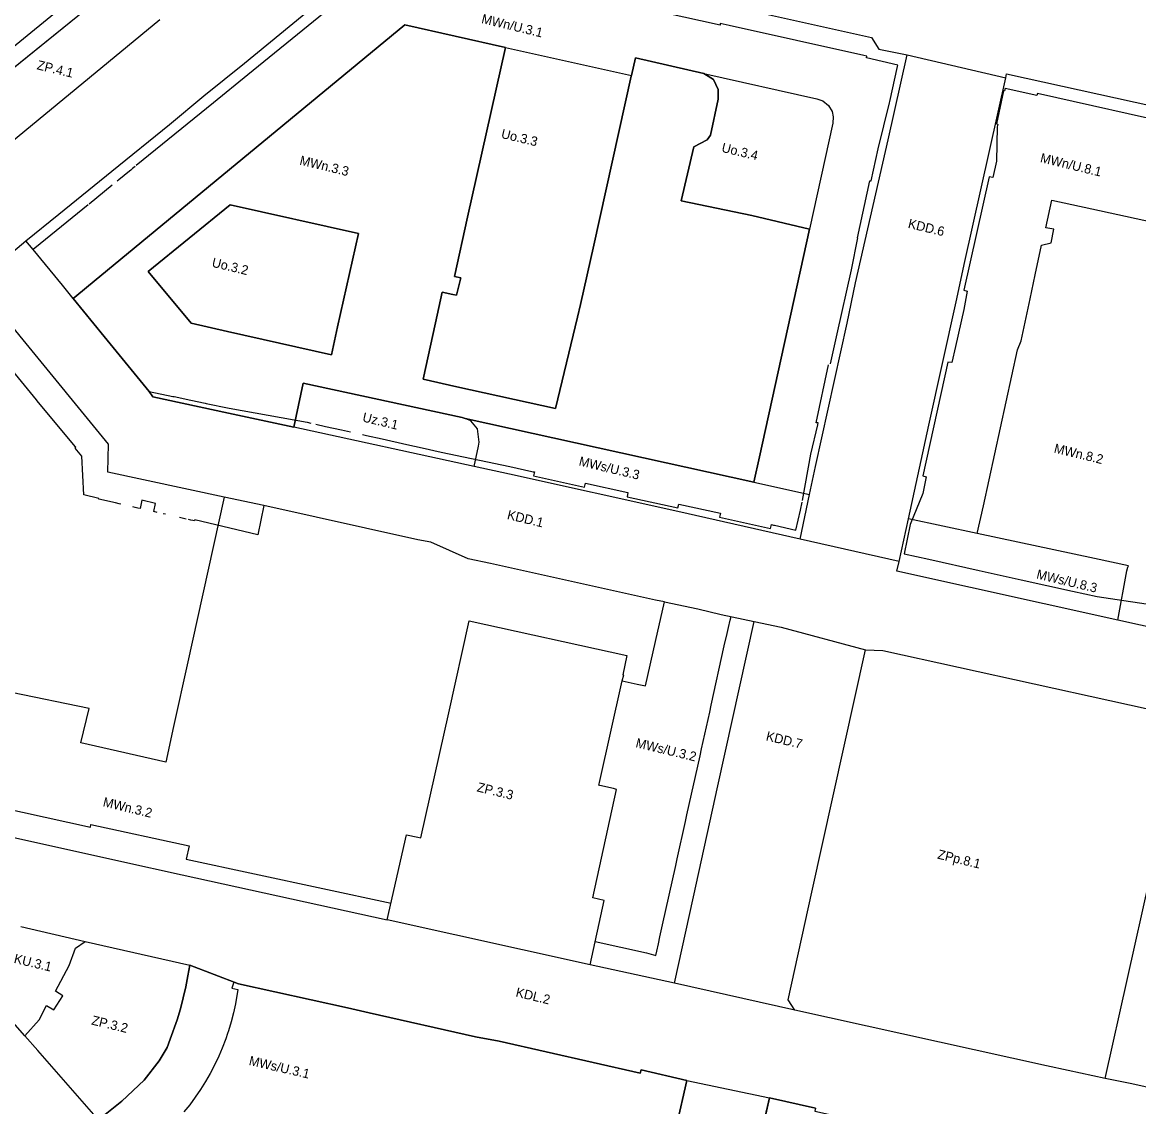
# Model space of a CAD drawing. Extents: x 7429686 to 7432896, y 5547954 to 5550600.
# Drawn here: x 7430853.5 to 7431331.5, y 5549169.6 to 5549633.8 of the extents above; entities that cross this region are included whole.
import ezdxf

# ---------------------------------------------------------------- set-up
doc = ezdxf.new("R2010")
doc.units = 0
for name, color, linetype in [('linie rozgraniczające', 7, 'Continuous'), ('obowiązująca linia zabudowy', 7, 'Continuous'), ('oznaczenia przeznaczeń', 7, 'Continuous')]:
    doc.layers.add(name, color=color, linetype=linetype)

msp = doc.modelspace()

# ---------------------------------------------------------------- linework, layer by layer
at = {"layer": 'linie rozgraniczające'}
for p, q in [((7430805.78, 5549578.76), (7430902.46, 5549657.05)), ((7431060.44, 5549622.97), (7431017.3, 5549632.77)), ((7431145.35, 5549611.95), (7431115.98, 5549618.56)), ((7431149.4, 5549609.29), (7431145.35, 5549611.95)), ((7431151.42, 5549605.07), (7431149.4, 5549609.29)), ((7431151.36, 5549600.9), (7431151.42, 5549605.07)), ((7431148.1, 5549585.52), (7431151.36, 5549600.9)), ((7431146.68, 5549583.47), (7431148.1, 5549585.52)), ((7431165.82, 5549551.11), (7431135.61, 5549557.36)), ((7431190.58, 5549545.27), (7431165.82, 5549551.11)), ((7430997.37, 5549543.36), (7430988.46, 5549503.38)), ((7430925.73, 5549504.96), (7430907.34, 5549527.16)), ((7430941.32, 5549501.47), (7430925.73, 5549504.96)), ((7430985.82, 5549491.51), (7430941.32, 5549501.47)), ((7430988.46, 5549503.38), (7430985.82, 5549491.51)), ((7431043.13, 5549464.16), (7431166.77, 5549436.9)), ((7430925.21, 5549230.15), (7430924.39, 5549225.55)), ((7430946.07, 5549222.14), (7430925.21, 5549230.15)), ((7430924.39, 5549225.55), (7430923.56, 5549220.95)), ((7430992.68, 5549211.86), (7430946.07, 5549222.14)), ((7430921.28, 5549211.46), (7430919.72, 5549206.79)), ((7431057.72, 5549197.56), (7431047.54, 5549199.55)), ((7431137.98, 5549180.79), (7431118.39, 5549185.34)), ((7431173.39, 5549173.33), (7431168.91, 5549153.67)), ((7431193.1, 5549168.9), (7431173.39, 5549173.33))]:
    msp.add_line(p, q, dxfattribs=at)
for points in [[(7430948.56, 5549616.32), (7431013.19, 5549669.37)], [(7430902.46, 5549657.05), (7430805.78, 5549578.76)], [(7431154.15, 5549641.32), (7431217.12, 5549627.23)], [(7430912.39, 5549634.82), (7430824.34, 5549562.34)], [(7431017.3, 5549632.77), (7430884.31, 5549522.94), (7430876.89, 5549516.82), (7430875.29, 5549515.5)], [(7430875.29, 5549515.5), (7430876.89, 5549516.82), (7430884.31, 5549522.94), (7431017.3, 5549632.77), (7431060.44, 5549622.97)], [(7431217.12, 5549627.23), (7431220.25, 5549622.33)], [(7431041.28, 5549524.35), (7431038.58, 5549525.03), (7431044.08, 5549550.36), (7431060.44, 5549622.97)], [(7431060.44, 5549622.97), (7431044.08, 5549550.36)], [(7431060.44, 5549622.97), (7431114.3, 5549611.01)], [(7431115.98, 5549618.56), (7431114.3, 5549611.01), (7431114.25, 5549610.75)], [(7431114.3, 5549611.01), (7431115.98, 5549618.56), (7431145.35, 5549611.95)], [(7431220.25, 5549622.33), (7431232.35, 5549619.87)], [(7431224.18, 5549583.49), (7431232.35, 5549619.87)], [(7431232.35, 5549619.87), (7431274.57, 5549610.08)], [(7430931.23, 5549602.33), (7430948.56, 5549616.32)], [(7431044.08, 5549550.36), (7431038.58, 5549525.03), (7431041.28, 5549524.35), (7431039.37, 5549516.99), (7431037.88, 5549517.3), (7431033.27, 5549518.26), (7431030.39, 5549505.08), (7431025.15, 5549481), (7431039.49, 5549477.82), (7431081.71, 5549468.44), (7431091.22, 5549507.55), (7431092.54, 5549512.97), (7431098.15, 5549538.37), (7431114.25, 5549610.75), (7431114.3, 5549611.01)], [(7431114.25, 5549610.75), (7431098.15, 5549538.37), (7431092.54, 5549512.97), (7431091.22, 5549507.55), (7431081.71, 5549468.44)], [(7431145.35, 5549611.95), (7431149.4, 5549609.29), (7431151.42, 5549605.07), (7431151.36, 5549600.9), (7431148.1, 5549585.52), (7431146.68, 5549583.47), (7431141.02, 5549580.54), (7431135.61, 5549557.36), (7431165.82, 5549551.11), (7431190.58, 5549545.27)], [(7431145.35, 5549611.95), (7431193.69, 5549601.09)], [(7431257.06, 5549531.37), (7431274.57, 5549610.08)], [(7431274.57, 5549610.08), (7431274.89, 5549611.78)], [(7431274.89, 5549611.78), (7431345.61, 5549596.13)], [(7430916.56, 5549590.09), (7430931.23, 5549602.33)], [(7431193.69, 5549601.09), (7431196.23, 5549600.17)], [(7431196.23, 5549600.17), (7431198.63, 5549598.17)], [(7431198.63, 5549598.17), (7431200.21, 5549595.65)], [(7431200.21, 5549595.65), (7431200.74, 5549593.29)], [(7430891.82, 5549570.05), (7430916.56, 5549590.09)], [(7431200.57, 5549590.67), (7431190.58, 5549545.27)], [(7431200.74, 5549593.29), (7431200.57, 5549590.67)], [(7431135.61, 5549557.36), (7431141.02, 5549580.54), (7431146.68, 5549583.47)], [(7431210.29, 5549522.31), (7431224.18, 5549583.49)], [(7430869.05, 5549551.6), (7430891.82, 5549570.05)], [(7431291.74, 5549545.78), (7431294.36, 5549557.7)], [(7431294.36, 5549557.7), (7431311.49, 5549553.94)], [(7430985.82, 5549491.51), (7430988.46, 5549503.38), (7430997.37, 5549543.36), (7430942.5, 5549555.67), (7430907.34, 5549527.16), (7430925.73, 5549504.96)], [(7430907.34, 5549527.16), (7430942.5, 5549555.67), (7430997.37, 5549543.36)], [(7431311.49, 5549553.94), (7431344.79, 5549546.64)], [(7430854.97, 5549540.19), (7430869.05, 5549551.6)], [(7431166.77, 5549436.9), (7431169.16, 5549447.78), (7431190.58, 5549545.27)], [(7431190.58, 5549545.27), (7431169.16, 5549447.78), (7431166.77, 5549436.9)], [(7431295.13, 5549545.22), (7431291.74, 5549545.78)], [(7431294.06, 5549539.34), (7431295.13, 5549545.22)], [(7430833.75, 5549522.41), (7430854.97, 5549540.19)], [(7430858.13, 5549536.5), (7430854.97, 5549540.19)], [(7431287.21, 5549525.72), (7431289.93, 5549538.36)], [(7431289.93, 5549538.36), (7431294.06, 5549539.34)], [(7430870.63, 5549521.22), (7430858.13, 5549536.5)], [(7431253.27, 5549514.13), (7431257.06, 5549531.37)], [(7431081.71, 5549468.44), (7431039.49, 5549477.82), (7431025.15, 5549481), (7431030.39, 5549505.08), (7431033.27, 5549518.26), (7431037.88, 5549517.3), (7431039.37, 5549516.99), (7431041.28, 5549524.35)], [(7431285, 5549515.41), (7431287.21, 5549525.72)], [(7430853.78, 5549497.92), (7430833.75, 5549522.41)], [(7430875.29, 5549515.5), (7430870.63, 5549521.22)], [(7431206.62, 5549504.99), (7431210.29, 5549522.31)], [(7430875.29, 5549515.5), (7430888.55, 5549499.33), (7430907.83, 5549475.8), (7430909.41, 5549473.4), (7430941.7, 5549466.42), (7430969.78, 5549460.53)], [(7430969.78, 5549460.53), (7430941.7, 5549466.42), (7430909.41, 5549473.4), (7430907.83, 5549475.8), (7430888.55, 5549499.33), (7430875.29, 5549515.5)], [(7431241.65, 5549461.33), (7431253.27, 5549514.13)], [(7431281.12, 5549497.39), (7431285, 5549515.41)], [(7430925.73, 5549504.96), (7430941.32, 5549501.47), (7430985.82, 5549491.51)], [(7431193.11, 5549443.59), (7431206.62, 5549504.99)], [(7430890.32, 5549453.23), (7430853.78, 5549497.92)], [(7431279.64, 5549493.6), (7431281.12, 5549497.39)], [(7431264.99, 5549426.8), (7431279.64, 5549493.6)], [(7430969.78, 5549460.53), (7430973.73, 5549479.35), (7431041.84, 5549464.68), (7431043.13, 5549464.16)], [(7431043.13, 5549464.16), (7431041.84, 5549464.68), (7430973.73, 5549479.35), (7430969.78, 5549460.53)], [(7431045.53, 5549463.19), (7431043.13, 5549464.16)], [(7431166.77, 5549436.9), (7431043.13, 5549464.16)], [(7431048.41, 5549459.82), (7431045.53, 5549463.19)], [(7431232.88, 5549421.31), (7431241.65, 5549461.33)], [(7431046.95, 5549443.71), (7430969.78, 5549460.53)], [(7431049.16, 5549454.04), (7431048.41, 5549459.82)], [(7430890.1, 5549441.28), (7430890.32, 5549453.23)], [(7431046.95, 5549443.71), (7431048.8, 5549452.38)], [(7431048.8, 5549452.38), (7431049.16, 5549454.04)], [(7431062.15, 5549440.39), (7431046.95, 5549443.71)], [(7431190.57, 5549431.65), (7431193.11, 5549443.59)], [(7430939.91, 5549430.52), (7430890.1, 5549441.28)], [(7431134.22, 5549424.35), (7431062.15, 5549440.39)], [(7431166.77, 5549436.9), (7431190.57, 5549431.65)], [(7430939.91, 5549430.52), (7430926.22, 5549368.37)], [(7430956.92, 5549426.98), (7430939.91, 5549430.52)], [(7431186.51, 5549412.5), (7431190.57, 5549431.65)], [(7431022.86, 5549412.27), (7430956.92, 5549426.98)], [(7431186.51, 5549412.5), (7431134.22, 5549424.35)], [(7431262.39, 5549414.97), (7431264.99, 5549426.8)], [(7431228.87, 5549403.02), (7431232.88, 5549421.31)], [(7431262.39, 5549414.97), (7431232.88, 5549421.31)], [(7431312.51, 5549404.2), (7431262.39, 5549414.97)], [(7431028.36, 5549411.26), (7431022.86, 5549412.27)], [(7431044.33, 5549404.06), (7431028.36, 5549411.26)], [(7431228.87, 5549403.02), (7431186.51, 5549412.5)], [(7431053.95, 5549402.07), (7431044.33, 5549404.06)], [(7431327.11, 5549401.06), (7431312.51, 5549404.2)], [(7431124.6, 5549386.43), (7431053.95, 5549402.07)], [(7431227.95, 5549398.82), (7431228.87, 5549403.02)], [(7431322.62, 5549377.89), (7431227.95, 5549398.82)], [(7431322.62, 5549377.89), (7431326.44, 5549398.92)], [(7431326.44, 5549398.92), (7431326.91, 5549400.58)], [(7431326.91, 5549400.58), (7431327.11, 5549401.06)], [(7431124.55, 5549368.66), (7431128.39, 5549385.66)], [(7431128.39, 5549385.66), (7431124.6, 5549386.43)], [(7431128.39, 5549385.66), (7431142.66, 5549382.73)], [(7431142.66, 5549382.73), (7431152.75, 5549380.32)], [(7431152.75, 5549380.32), (7431166.9, 5549377.31)], [(7431036.05, 5549338.21), (7431044.85, 5549377.6)], [(7431044.85, 5549377.6), (7431112.37, 5549362.8)], [(7431151.26, 5549306.99), (7431166.9, 5549377.31)], [(7431166.9, 5549377.31), (7431178.43, 5549374.88)], [(7431178.43, 5549374.88), (7431214.54, 5549365.17)], [(7431444.94, 5549350.86), (7431322.62, 5549377.89)], [(7430926.22, 5549368.37), (7430924.39, 5549360.07)], [(7431120.27, 5549349.73), (7431124.55, 5549368.66)], [(7431112.37, 5549362.8), (7431110.56, 5549354.5)], [(7431191.59, 5549261.43), (7431214.54, 5549365.17)], [(7431214.54, 5549365.17), (7431221.89, 5549364.84)], [(7431221.89, 5549364.84), (7431351.47, 5549336.38)], [(7430924.39, 5549360.07), (7430918.27, 5549332.28)], [(7431100.69, 5549308.41), (7431110.39, 5549351.83)], [(7431110.39, 5549351.85), (7431111.1, 5549354.42)], [(7431110.39, 5549351.83), (7431110.39, 5549351.85)], [(7431110.39, 5549351.83), (7431116.68, 5549350.49)], [(7431110.56, 5549354.5), (7431111.1, 5549354.42)], [(7430882.06, 5549340.05), (7430848.84, 5549346.95)], [(7431116.68, 5549350.49), (7431120.27, 5549349.73)], [(7430878.53, 5549325.34), (7430882.06, 5549340.05)], [(7431024.08, 5549284.61), (7431036.05, 5549338.21)], [(7430918.27, 5549332.28), (7430914.91, 5549317.04)], [(7430881.65, 5549324.62), (7430878.53, 5549325.34)], [(7430914.91, 5549317.04), (7430881.65, 5549324.62)], [(7431100.29, 5549307.16), (7431100.69, 5549308.41)], [(7431097.72, 5549259.01), (7431107.87, 5549305.41)], [(7431100.78, 5549307.05), (7431100.29, 5549307.16)], [(7431106.56, 5549305.73), (7431100.78, 5549307.05)], [(7431107.87, 5549305.41), (7431106.56, 5549305.73)], [(7431140.83, 5549259.37), (7431151.26, 5549306.99)], [(7430833.66, 5549288.37), (7430896.14, 5549274.49)], [(7431009.76, 5549249.53), (7431017.92, 5549285.99)], [(7431017.92, 5549285.99), (7431022.8, 5549284.9)], [(7431022.8, 5549284.9), (7431024.08, 5549284.61)], [(7430896.14, 5549274.49), (7430921.88, 5549268.85)], [(7430921.88, 5549268.85), (7431009.76, 5549249.53)], [(7431317.19, 5549181.59), (7431336.22, 5549267.3)], [(7431181.37, 5549215.29), (7431191.59, 5549261.43)], [(7431096.56, 5549230.3), (7431102.59, 5549257.84)], [(7431102.59, 5549257.84), (7431097.72, 5549259.01)], [(7431132.72, 5549222.39), (7431140.83, 5549259.37)], [(7430852.85, 5549246.65), (7430880.45, 5549240.36)], [(7431096.56, 5549230.3), (7431009.76, 5549249.53)], [(7430873.55, 5549229.96), (7430876.26, 5549237.45)], [(7430876.26, 5549237.45), (7430880.45, 5549240.36)], [(7430880.45, 5549240.36), (7430925.21, 5549230.15)], [(7430867.65, 5549218.97), (7430873.55, 5549229.96)], [(7430886.17, 5549163.92), (7430896.16, 5549171.92), (7430905.64, 5549181), (7430912.06, 5549189.23), (7430915.45, 5549194.85), (7430916.8, 5549198.49), (7430919.72, 5549206.79), (7430921.28, 5549211.46), (7430922.42, 5549216.2), (7430923.56, 5549220.95), (7430924.39, 5549225.55), (7430925.21, 5549230.15)], [(7430925.21, 5549230.15), (7430946.07, 5549222.14), (7430992.68, 5549211.86), (7431002.04, 5549209.78), (7431047.54, 5549199.55), (7431057.72, 5549197.56), (7431118.08, 5549183.93), (7431118.39, 5549185.34), (7431137.98, 5549180.79)], [(7431132.72, 5549222.39), (7431096.56, 5549230.3)], [(7431184.19, 5549210.87), (7431132.72, 5549222.39)], [(7430866.94, 5549211.08), (7430870.85, 5549217.08)], [(7430870.85, 5549217.08), (7430867.65, 5549218.97)], [(7430923.56, 5549220.95), (7430922.42, 5549216.2), (7430921.28, 5549211.46)], [(7430860.67, 5549206.73), (7430863.87, 5549212.92)], [(7430863.87, 5549212.92), (7430866.94, 5549211.08)], [(7431184.19, 5549210.87), (7431181.37, 5549215.29)], [(7430854.62, 5549199.88), (7430846.27, 5549209.39)], [(7431047.54, 5549199.55), (7431002.04, 5549209.78), (7430992.68, 5549211.86)], [(7431291.99, 5549187.13), (7431184.19, 5549210.87)], [(7430854.62, 5549199.88), (7430860.67, 5549206.73)], [(7430919.72, 5549206.79), (7430916.8, 5549198.49), (7430915.45, 5549194.85), (7430912.06, 5549189.23), (7430905.64, 5549181)], [(7430860.07, 5549193.67), (7430854.62, 5549199.88)], [(7430886.17, 5549163.92), (7430860.07, 5549193.67)], [(7431118.39, 5549185.34), (7431118.08, 5549183.93), (7431057.72, 5549197.56)], [(7431301.28, 5549185.08), (7431291.99, 5549187.13)], [(7431317.19, 5549181.59), (7431301.28, 5549185.08)], [(7430905.64, 5549181), (7430896.16, 5549171.92), (7430886.17, 5549163.92)], [(7431099.36, 5548971.58), (7431107.22, 5549007.82), (7431113.56, 5549037.12), (7431098.96, 5549039.76), (7431100.87, 5549049.04), (7431122.56, 5549148.42), (7431126.27, 5549162.98), (7431133.65, 5549161.37), (7431137.98, 5549180.79)], [(7431137.98, 5549180.79), (7431133.65, 5549161.37), (7431126.27, 5549162.98)], [(7431137.98, 5549180.79), (7431173.39, 5549173.33)], [(7431327.86, 5549179.5), (7431317.19, 5549181.59)], [(7431417.65, 5549159.61), (7431327.86, 5549179.5)], [(7431135.08, 5549032.7), (7431149.76, 5549029.39), (7431151.58, 5549037.84), (7431176.31, 5549151.9), (7431168.91, 5549153.67), (7431173.39, 5549173.33)], [(7431173.39, 5549173.33), (7431193.1, 5549168.9), (7431192.85, 5549167.65), (7431263.81, 5549152.05), (7431318.87, 5549139.95), (7431392.81, 5549123.31), (7431392.8, 5549122.25), (7431398.12, 5549124.28), (7431424.93, 5549056.18)]]:
    msp.add_lwpolyline(points, dxfattribs=at)
at = {"layer": 'obowiązująca linia zabudowy'}
for p, q in [((7430891.99, 5549564.07), (7430882.1, 5549556.01)), ((7431193.42, 5549462.38), (7431198.73, 5549487.14)), ((7430879.82, 5549431.46), (7430878.95, 5549448.05)), ((7431186.64, 5549424.91), (7431187.42, 5549428.39)), ((7430914.73, 5549423.2), (7430913.73, 5549423.43)), ((7430923.66, 5549421.16), (7430920.77, 5549421.82))]:
    msp.add_line(p, q, dxfattribs=at)
for points in [[(7430807.75, 5549615.61), (7430820.21, 5549600.01), (7430823.08, 5549602.43), (7430823.42, 5549602.03), (7430938.16, 5549695.73)], [(7431082.3, 5549647.94), (7431032.15, 5549658.64), (7431013.1, 5549662.7), (7430950.02, 5549611.38), (7430935.36, 5549599.38)], [(7431228.2, 5549614.94), (7431228.3, 5549615.39), (7431214.88, 5549618.58), (7431215.1, 5549619.26), (7431213.86, 5549619.54), (7431156.17, 5549632.45), (7431152.34, 5549633.31), (7431152.22, 5549632.57), (7431104.29, 5549643.07), (7431082.3, 5549647.94)], [(7431224.85, 5549599.31), (7431224.99, 5549599.94), (7431228.2, 5549614.94)], [(7431274.25, 5549605.45), (7431274.07, 5549604.42), (7431273.6, 5549604.41), (7431270.67, 5549590.38), (7431271.15, 5549590.21), (7431270.95, 5549589.12), (7431270.6, 5549574.36), (7431268.97, 5549567.38), (7431267.54, 5549567.59), (7431256.57, 5549519.13), (7431258.06, 5549518.74), (7431256.56, 5549510.91), (7431253.1, 5549495.04), (7431251.42, 5549488.14), (7431249.79, 5549488.36), (7431239.13, 5549439.63), (7431240.54, 5549439.28), (7431239.01, 5549432.09), (7431233.68, 5549418.87), (7431231.1, 5549406.3), (7431241.6, 5549403.92), (7431263.18, 5549399.15), (7431281.16, 5549395.18), (7431303.22, 5549390.31), (7431313.77, 5549387.98), (7431343.19, 5549383.59)], [(7431388.08, 5549553.89), (7431390.82, 5549564.96), (7431392.34, 5549572.47), (7431393.73, 5549578.86), (7431350.33, 5549588.51), (7431350.59, 5549589.36), (7431288.19, 5549603.31), (7431287.93, 5549602.46), (7431274.25, 5549605.45)], [(7430935.36, 5549599.38), (7430902.27, 5549572.44)], [(7431208.59, 5549527.8), (7431211.26, 5549541.49), (7431211.07, 5549541.53), (7431216.42, 5549565.97), (7431216.95, 5549565.91), (7431219.87, 5549579.62), (7431224.85, 5549599.31)], [(7430901.76, 5549572.02), (7430901.24, 5549571.6), (7430900.72, 5549571.18), (7430899.95, 5549570.55), (7430899.39, 5549570.1), (7430894.74, 5549566.31), (7430894.06, 5549565.75)], [(7430881.65, 5549555.65), (7430861.08, 5549538.91), (7430858.13, 5549536.5)], [(7431199.58, 5549487.66), (7431202.39, 5549500.51), (7431208.59, 5549527.8)], [(7430859.5, 5549472.18), (7430838.81, 5549497.31), (7430827.62, 5549511.27), (7430818.17, 5549503.55), (7430821.09, 5549499.68)], [(7430907.83, 5549475.8), (7430917.95, 5549473.66), (7430918.21, 5549473.6), (7430918.48, 5549473.55), (7430925.66, 5549472.03), (7430931.77, 5549470.73), (7430932.24, 5549470.64), (7430942.08, 5549468.55)], [(7430878.95, 5549448.05), (7430876.07, 5549451.54), (7430876.34, 5549451.85), (7430876.05, 5549452.2), (7430859.86, 5549471.76), (7430859.5, 5549472.18)], [(7430942.08, 5549468.55), (7430975.39, 5549462.59), (7430976.98, 5549462.24)], [(7430979.1, 5549461.76), (7430983.36, 5549460.81), (7430990.19, 5549459.29), (7430993.96, 5549458.45)], [(7431187.57, 5549429.09), (7431191.13, 5549448.91), (7431194.04, 5549461.54), (7431194.21, 5549462.3), (7431193.42, 5549462.38)], [(7430999.19, 5549457.29), (7431000.84, 5549456.92), (7431007.58, 5549455.42), (7431018.07, 5549453.09), (7431024.74, 5549451.6), (7431032.82, 5549449.8)], [(7431032.82, 5549449.8), (7431062.22, 5549443.67), (7431071.69, 5549441.54)], [(7431071.69, 5549441.54), (7431071.69, 5549441.54), (7431072.19, 5549441.43), (7431072.5, 5549441.36), (7431072.75, 5549441.3), (7431072.39, 5549439.71)], [(7431072.39, 5549439.71), (7431094.24, 5549434.85), (7431094.63, 5549436.55), (7431112.75, 5549432.54), (7431112.44, 5549430.71), (7431134.12, 5549425.98), (7431134.59, 5549427.58), (7431152.42, 5549423.66), (7431152.05, 5549421.96), (7431173.91, 5549417.08), (7431174.23, 5549418.78), (7431174.74, 5549418.67), (7431175.12, 5549418.58), (7431175.51, 5549418.49), (7431184.75, 5549416.4), (7431186.64, 5549424.91)], [(7430895.61, 5549427.53), (7430894.96, 5549427.68), (7430893.34, 5549428.05), (7430886.23, 5549429.67), (7430886.28, 5549430.01), (7430879.82, 5549431.46)], [(7430911.17, 5549424.01), (7430909.85, 5549424.31), (7430910.53, 5549427.79), (7430904.68, 5549429.17), (7430903.9, 5549425.64), (7430902.88, 5549425.87), (7430901.82, 5549426.11), (7430900.84, 5549426.33)], [(7430956.92, 5549426.98), (7430954.28, 5549414.46), (7430927.38, 5549420.81), (7430927.2, 5549420.35), (7430926.48, 5549420.52), (7430925.65, 5549420.71), (7430924.62, 5549420.94)], [(7431098.73, 5549240.23), (7431120.69, 5549235.41), (7431124.68, 5549234.36), (7431125.12, 5549236.09), (7431125.83, 5549239.31), (7431126.48, 5549242.24), (7431127.63, 5549247.41), (7431133.26, 5549272.8), (7431133.91, 5549275.73), (7431137.46, 5549291.73), (7431138.07, 5549294.47), (7431143.7, 5549319.85), (7431144.34, 5549322.78), (7431147.83, 5549338.5), (7431148.48, 5549341.43), (7431154.07, 5549366.84), (7431155.32, 5549372.21), (7431155.89, 5549374.78), (7431156.54, 5549377.91), (7431157.04, 5549379.41)], [(7430755.67, 5549318.05), (7430774.38, 5549313.89), (7430774.18, 5549312.91), (7430813, 5549304.47), (7430813.33, 5549305.68), (7430844.07, 5549298.91), (7430843.76, 5549297.83), (7430882.61, 5549289.2), (7430882.88, 5549290.42), (7430924.94, 5549281.21), (7430923.68, 5549275.55), (7431011.35, 5549256.65)], [(7430944.02, 5549222.93), (7430943.26, 5549220.3), (7430945.69, 5549219.69), (7430944.76, 5549213.68), (7430943.87, 5549209.76), (7430942.91, 5549205.9), (7430941.73, 5549202.09), (7430941.33, 5549200.88), (7430940.58, 5549198.61), (7430939.05, 5549194.58), (7430937.63, 5549191.24), (7430935.72, 5549187.31), (7430933.89, 5549183.77), (7430931.89, 5549180.36), (7430929.74, 5549176.98), (7430927.52, 5549173.66), (7430925.14, 5549170.44), (7430922.6, 5549167.33)]]:
    msp.add_lwpolyline(points, dxfattribs=at)

# ---------------------------------------------------------------- texts
at = {"layer": 'oznaczenia przeznaczeń'}
for s, rotation, p in [('MWn/U.3.1', 346.4891, (7431049.82, 5549633.54)), ('ZP.4.1', 346.4891, (7430859.46, 5549613.74)), ('Uo.3.3', 346.4891, (7431058.24, 5549584.35)), ('Uo.3.4', 346.4891, (7431152.62, 5549578.39)), ('MWn.3.3', 346.4891, (7430971.95, 5549572.92)), ('MWn/U.8.1', 346.4891, (7431289.06, 5549573.99)), ('KDD.6', 346.4891, (7431232.45, 5549545.87)), ('Uo.3.2', 346.5122, (7430934.37, 5549529.21)), ('Uz.3.1', 346.4891, (7430998.86, 5549462.97)), ('MWn.8.2', 346.4891, (7431294.96, 5549449.64)), ('MWs/U.3.3', 346.4891, (7431091.52, 5549444.14)), ('KDD.1', 346.4891, (7431060.81, 5549421.22)), ('MWs/U.8.3', 346.5122, (7431287.45, 5549395.76)), ('MWs/U.3.2', 346.4891, (7431115.84, 5549323.53)), ('KDD.7', 346.4891, (7431171.64, 5549326.48)), ('ZP.3.3', 346.4891, (7431047.87, 5549304.61)), ('MWn.3.2', 346.5122, (7430887.73, 5549298.23)), ('ZPp.8.1', 346.4891, (7431245.07, 5549275.84)), ('KU.3.1', 346.4891, (7430849.62, 5549231.21)), ('KDL.2', 346.4891, (7431064.48, 5549216.79)), ('ZP.3.2', 346.4891, (7430882.82, 5549204.79)), ('MWs/U.3.1', 347.0609, (7430950.25, 5549187.48))]:
    msp.add_text(s, height=4, rotation=rotation, dxfattribs=at).set_placement(p)

doc.saveas('drawing.dxf')
